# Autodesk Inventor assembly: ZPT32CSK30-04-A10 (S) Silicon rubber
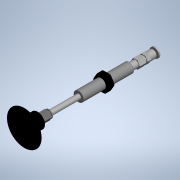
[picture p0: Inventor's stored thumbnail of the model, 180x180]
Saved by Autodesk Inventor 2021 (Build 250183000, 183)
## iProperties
Part Number: ZPT32CSK30-04-A10 (S) Silicon rubber
Catalog Web Link: www.cadenas.de
Description: ZPT-Pad Diameter Dia 20-32
Vendor: SMC
Document SubType Name: Assembly
Designer: partserver
Manufacturer: SMC
Mass: 9.11327 g
Surface Area: 77.6499 cm^2
Volume: 9.11327 cm^3
Density: 1 g/cm^3
Category: PARTsolutions
Company: SMC
PSOL_IDENT_0: {$CADENAS_DATA\23d-libs\smc_jp\vacuum_equipment\vacuum_pad\zp\zpt_b\zpt_20_32_b_asmtab.prj},217 {VTY
PSOL_IDENT_1: P=3D},{STYP=ASSTAB},{NB=ZPT32CSK30-04-A10},{LINA=ZPT32CSK30-04-A10},{NN=ZPT},{DATE=12.02.2021 09:21:
PSOL_IDENT_2: 58},{GEOMDATE=29.10.2020 08:50:08},{VERSION=},{LINEID=130},{WBVAR=MATERIAL,TYPE,STROKE,PORT},{WBNUME
PSOL_IDENT_3: RIC=STROKE}  {NB=ZPT32CSK30-04-A10},{LINA=ZPT32CSK30-04-A10},{KT=DUMMY},{DIAMETER=32},{PAD=(C) Flat
PSOL_IDENT_4: with ribs},{PADX=C},{MATERIAL=S},{TYPE=K},{STROKE=30},{PORT=04},{MOUNT=(A10) M10x1 (Male thread)},{O
PSOL_IDENT_5: RDER=ZPT32CSK30-04-A10},{TIF=C2},{PPATH=zpt_20_32_b/assembly/zpt_20_32_b_asmsbl.prj},{MODEL=ZPT32CSK
PSOL_IDENT_6: 30-04-A10},{NENN=ZPT32C}
NB: ZPT32CSK30-04-A10
NN: ZPT
NT: Pad Diameter Dia 20-32
NBSYN: $ORDER.
LINA: ZPT32CSK30-04-A10
CATALOG: SMC (JP
DIAMETER: 32
PAD: (C) Flat with ribs
MATERIAL: (S) Silicon rubber
TYPE: (K) Non-rotating
STROKE: 30
PORT: (04) dia 4 tube (One-touch fitting)
MOUNT: (A10) M10x1 (Male thread)
SUPPLIER: SMC
ARTICLENO: ZPT32CSK30-04-A10
BOMINFO: ZPT32CSK30-04-A10
CREATOR: CADENAS GmbH
Title: ZPT32CSK30-04-A10
Author: Cadenas PARTsolutions
Comments: Pad Diameter Dia 20-32
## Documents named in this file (6)
- D:\01 Paralaia\Grupos de Traballo\GT Maquetas\CAD 3D\E_AlimentaciónV1\ZPT32SCK30\ZPT32CSK30-04-A10_(S) Silicon rubber.iam
- D:\01 Paralaia\Grupos de Traballo\GT Maquetas\CAD 3D\E_AlimentaciónV1\ZPT32SCK30\ZP32C_T_B.ipt
- D:\01 Paralaia\Grupos de Traballo\GT Maquetas\CAD 3D\E_AlimentaciónV1\ZPT32SCK30\ZPT20_32_B_ADAPTER.ipt
- D:\01 Paralaia\Grupos de Traballo\GT Maquetas\CAD 3D\E_AlimentaciónV1\ZPT32SCK30\ZPT32C30-04-A10_B_BUFFER.ipt
- D:\01 Paralaia\Grupos de Traballo\GT Maquetas\CAD 3D\E_AlimentaciónV1\ZPT32SCK30\ZPT20_32_B_NUT.ipt
- D:\01 Paralaia\Grupos de Traballo\GT Maquetas\CAD 3D\E_AlimentaciónV1\ZPT32SCK30\Rosca.ipt
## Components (6 placed, 5 different names)
1. ZP32C_T_B:1
2. ZPT20_32_B_ADAPTER:1
3. ZPT32C30-04-A10_B_BUFFER:1
4. ZPT20_32_B_NUT:1
5. ZPT20_32_B_NUT:2
6. Rosca:1 — Insertar:1
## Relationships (1: Insert 1)
- Insertar:1: Rosca:1
